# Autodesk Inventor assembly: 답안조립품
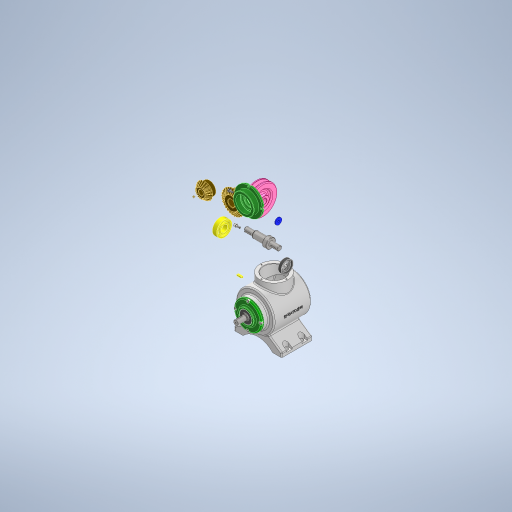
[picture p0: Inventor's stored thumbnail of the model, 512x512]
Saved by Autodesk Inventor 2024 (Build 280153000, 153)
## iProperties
Created: 2023-08
Part Number: 답안조립품
Document SubType Name: Assembly
Designer: Owner
Author: Owner
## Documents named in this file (17)
- C:\Users\Owner\Desktop\730813V1007\답안조립품.iam
- C:\Users\Owner\Desktop\730813V1007\본체.ipt
- C:\Users\Owner\Desktop\730813V1007\V-벨트풀리.ipt
- C:\Users\Owner\Desktop\730813V1007\메인 베벨기어.ipt
- C:\Users\Owner\Desktop\730813V1007\메인 축.ipt
- 메인 축.ipt
- C:\Users\Owner\Desktop\730813V1007\베어링 6203.ipt
- C:\Users\Owner\Desktop\730813V1007\볼트 M4 x 10.ipt
- C:\Users\Owner\Desktop\730813V1007\서브 베벨기어.ipt
- C:\Users\Owner\Desktop\730813V1007\서브 축.ipt
- 서브 축.ipt
- C:\Users\Owner\Desktop\730813V1007\오일실 17 x 32 x 8.ipt
- C:\Users\Owner\Desktop\730813V1007\와셔 4 x 16.ipt
- C:\Users\Owner\Desktop\730813V1007\육각볼트 M4 x 8.ipt
- C:\Users\Owner\Desktop\730813V1007\커버.ipt
- C:\Users\Owner\Desktop\730813V1007\키 4 x 4 x 14.ipt
- C:\Users\Owner\Desktop\730813V1007\키 5 x 5 x 14.ipt
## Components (1 placed, 1 different names)
1. V-벨트풀리:1
